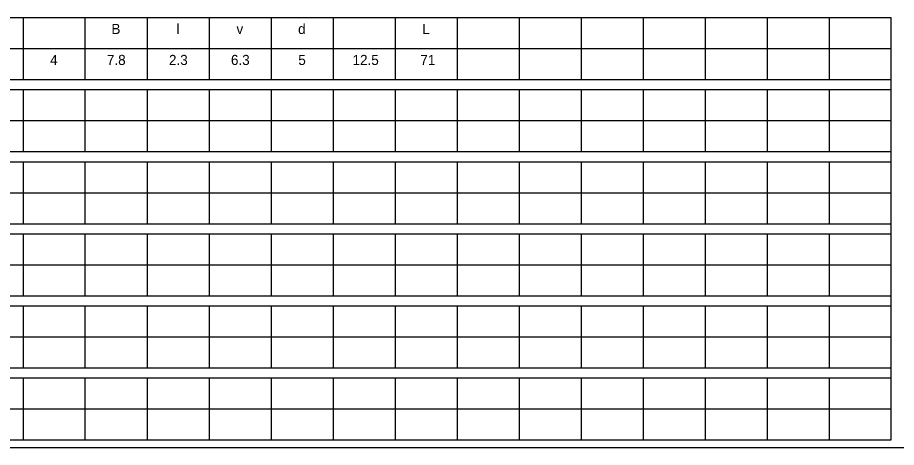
# Model space of a CAD drawing. Extents: x -998.8 to -961.2, y -2311.8 to -2287.8.
# Drawn here: x -990.75 to -980.09, y -2311.26 to -2306.05 of the extents above; entities that cross this region are included whole.
import ezdxf

# ---------------------------------------------------------------- set-up
doc = ezdxf.new("R2010")
doc.units = 0
doc.layers.add('GSSign', color=7, linetype='Continuous')
doc.layers.add('SheetLinesMisc2_dp', color=7, linetype='Continuous')

msp = doc.modelspace()

# ---------------------------------------------------------------- linework, layer by layer
at = {"layer": 'SheetLinesMisc2_dp'}
for p, q in [((-998.646, -2306.048), (-980.149, -2306.048)), ((-990.683, -2306.048), (-990.683, -2306.8)), ((-989.931, -2306.048), (-989.931, -2306.8)), ((-989.178, -2306.048), (-989.178, -2306.8)), ((-988.426, -2306.048), (-988.426, -2306.8)), ((-987.673, -2306.048), (-987.673, -2306.8)), ((-986.921, -2306.048), (-986.921, -2306.8)), ((-986.168, -2306.048), (-986.168, -2306.8)), ((-985.416, -2306.048), (-985.416, -2306.8)), ((-984.664, -2306.048), (-984.664, -2306.8)), ((-983.911, -2306.048), (-983.911, -2306.8)), ((-983.159, -2306.048), (-983.159, -2306.8)), ((-982.406, -2306.048), (-982.406, -2306.8)), ((-981.654, -2306.048), (-981.654, -2306.8)), ((-980.901, -2306.048), (-980.901, -2306.8)), ((-980.149, -2311.17), (-980.149, -2306.048)), ((-998.646, -2306.424), (-980.149, -2306.424)), ((-998.646, -2306.8), (-980.149, -2306.8)), ((-998.646, -2306.922), (-980.149, -2306.922)), ((-990.683, -2306.922), (-990.683, -2307.674)), ((-989.931, -2306.922), (-989.931, -2307.674)), ((-989.178, -2306.922), (-989.178, -2307.674)), ((-988.426, -2306.922), (-988.426, -2307.674)), ((-987.673, -2306.922), (-987.673, -2307.674)), ((-986.921, -2306.922), (-986.921, -2307.674)), ((-986.168, -2306.922), (-986.168, -2307.674)), ((-985.416, -2306.922), (-985.416, -2307.674)), ((-984.664, -2306.922), (-984.664, -2307.674)), ((-983.911, -2306.922), (-983.911, -2307.674)), ((-983.159, -2306.922), (-983.159, -2307.674)), ((-982.406, -2306.922), (-982.406, -2307.674)), ((-981.654, -2306.922), (-981.654, -2307.674)), ((-980.901, -2306.922), (-980.901, -2307.674)), ((-998.646, -2307.298), (-980.149, -2307.298)), ((-998.646, -2307.674), (-980.149, -2307.674)), ((-998.646, -2307.796), (-980.149, -2307.796)), ((-990.683, -2307.796), (-990.683, -2308.548)), ((-989.931, -2307.796), (-989.931, -2308.548)), ((-989.178, -2307.796), (-989.178, -2308.548)), ((-988.426, -2307.796), (-988.426, -2308.548)), ((-987.673, -2307.796), (-987.673, -2308.548)), ((-986.921, -2307.796), (-986.921, -2308.548)), ((-986.168, -2307.796), (-986.168, -2308.548)), ((-985.416, -2307.796), (-985.416, -2308.548)), ((-984.664, -2307.796), (-984.664, -2308.548)), ((-983.911, -2307.796), (-983.911, -2308.548)), ((-983.159, -2307.796), (-983.159, -2308.548)), ((-982.406, -2307.796), (-982.406, -2308.548)), ((-981.654, -2307.796), (-981.654, -2308.548)), ((-980.901, -2307.796), (-980.901, -2308.548)), ((-998.646, -2308.172), (-980.149, -2308.172)), ((-998.646, -2308.548), (-980.149, -2308.548)), ((-998.646, -2308.67), (-980.149, -2308.67)), ((-990.683, -2308.67), (-990.683, -2309.422)), ((-989.931, -2308.67), (-989.931, -2309.422)), ((-989.178, -2308.67), (-989.178, -2309.422)), ((-988.426, -2308.67), (-988.426, -2309.422)), ((-987.673, -2308.67), (-987.673, -2309.422)), ((-986.921, -2308.67), (-986.921, -2309.422)), ((-986.168, -2308.67), (-986.168, -2309.422)), ((-985.416, -2308.67), (-985.416, -2309.422)), ((-984.664, -2308.67), (-984.664, -2309.422)), ((-983.911, -2308.67), (-983.911, -2309.422)), ((-983.159, -2308.67), (-983.159, -2309.422)), ((-982.406, -2308.67), (-982.406, -2309.422)), ((-981.654, -2308.67), (-981.654, -2309.422)), ((-980.901, -2308.67), (-980.901, -2309.422)), ((-998.646, -2309.046), (-980.149, -2309.046)), ((-998.646, -2309.422), (-980.149, -2309.422)), ((-998.646, -2309.544), (-980.149, -2309.544)), ((-990.683, -2309.544), (-990.683, -2310.296)), ((-989.931, -2309.544), (-989.931, -2310.296)), ((-989.178, -2309.544), (-989.178, -2310.296)), ((-988.426, -2309.544), (-988.426, -2310.296)), ((-987.673, -2309.544), (-987.673, -2310.296)), ((-986.921, -2309.544), (-986.921, -2310.296)), ((-986.168, -2309.544), (-986.168, -2310.296)), ((-985.416, -2309.544), (-985.416, -2310.296)), ((-984.664, -2309.544), (-984.664, -2310.296)), ((-983.911, -2309.544), (-983.911, -2310.296)), ((-983.159, -2309.544), (-983.159, -2310.296)), ((-982.406, -2309.544), (-982.406, -2310.296)), ((-981.654, -2309.544), (-981.654, -2310.296)), ((-980.901, -2309.544), (-980.901, -2310.296)), ((-998.646, -2309.92), (-980.149, -2309.92)), ((-998.646, -2310.296), (-980.149, -2310.296)), ((-998.646, -2310.418), (-980.149, -2310.418)), ((-990.683, -2310.418), (-990.683, -2311.17)), ((-989.931, -2310.418), (-989.931, -2311.17)), ((-989.178, -2310.418), (-989.178, -2311.17)), ((-988.426, -2310.418), (-988.426, -2311.17)), ((-987.673, -2310.418), (-987.673, -2311.17)), ((-986.921, -2310.418), (-986.921, -2311.17)), ((-986.168, -2310.418), (-986.168, -2311.17)), ((-985.416, -2310.418), (-985.416, -2311.17)), ((-984.664, -2310.418), (-984.664, -2311.17)), ((-983.911, -2310.418), (-983.911, -2311.17)), ((-983.159, -2310.418), (-983.159, -2311.17)), ((-982.406, -2310.418), (-982.406, -2311.17)), ((-981.654, -2310.418), (-981.654, -2311.17)), ((-980.901, -2310.418), (-980.901, -2311.17)), ((-998.646, -2310.794), (-980.149, -2310.794)), ((-998.646, -2311.17), (-980.149, -2311.17)), ((-998.826, -2311.261), (-961.216, -2311.261))]:
    msp.add_line(p, q, dxfattribs=at)

# ---------------------------------------------------------------- texts
at = {"layer": 'GSSign'}
for s, height, p in [('B', 0.123, (-989.61, -2306.247)), ('l', 0.123, (-988.82, -2306.247)), ('v', 0.123, (-988.093, -2306.247)), ('d', 0.123, (-987.345, -2306.247)), ('L', 0.123, (-985.84, -2306.247)), ('4', 0.123, (-990.354, -2306.623)), ('7.8', 0.1225, (-989.665, -2306.623)), ('2.3', 0.1225, (-988.912, -2306.623)), ('6.3', 0.1225, (-988.16, -2306.623)), ('5', 0.123, (-987.343, -2306.623)), ('12.5', 0.1225, (-986.685, -2306.623)), ('71', 0.1225, (-985.862, -2306.623))]:
    msp.add_text(s, height=height, dxfattribs=at).set_placement(p)

doc.saveas('drawing.dxf')
